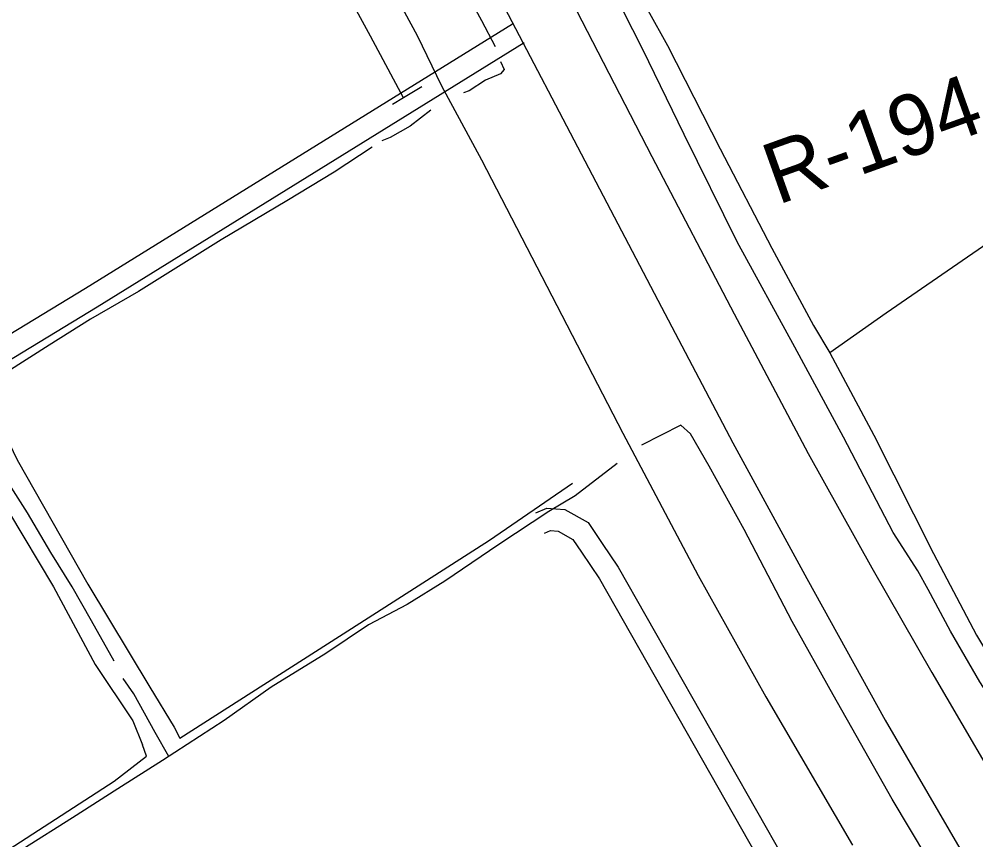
# Model space of a CAD drawing. Extents: x 3324125 to 3362000, y 600753 to 626151.
# Drawn here: x 3330131 to 3331430, y 613099 to 614214 of the extents above; entities that cross this region are included whole.
import ezdxf

# ---------------------------------------------------------------- set-up
doc = ezdxf.new("R2010")
doc.units = 0
for name, color, linetype in [('V-DTCH-CNTR', 7, 'Continuous'), ('V-RAIL-TRAK', 7, 'Continuous'), ('V-RIVR-RANG-IDEN', 7, 'Continuous'), ('V-ROAD-CNTR', 7, 'Continuous'), ('V-TOPO-SHOR', 7, 'Continuous')]:
    doc.layers.add(name, color=color, linetype=linetype)

msp = doc.modelspace()

# ---------------------------------------------------------------- linework, layer by layer
at = {"layer": 'V-DTCH-CNTR'}
for points in [[(3330957.7, 614274.3), (3331010.7, 614177.8), (3331082.2, 614037.5), (3331152.6, 613902.5), (3331209.1, 613797.3), (3331231.5, 613760.5), (3331290.9, 613648.4), (3331372.2, 613487.5), (3331430.4, 613376.6), (3331510.5, 613243.8), (3331602.7, 613085.8)], [(3331480.9, 613933.3), (3331307.9, 613814.1), (3331231.5, 613760.5)], [(3329967.9, 613897.1), (3330014.9, 613810.6), (3330059.1, 613727.8), (3330072, 613718.1), (3330082.6, 613708.4), (3330128, 613614.7), (3330223.6, 613445.8), (3330307.9, 613306), (3330341.1, 613251.9)], [(3330020.6, 613705), (3330062.9, 613630.2), (3330115.9, 613544.7), (3330177.2, 613442.6), (3330233.8, 613337), (3330285, 613260.4), (3330298.1, 613227.7)], [(3330341.1, 613251.9), (3330348.8, 613236.8), (3330581.7, 613385.7), (3330769.2, 613506), (3330882, 613583.3)], [(3329755.3, 612855.6), (3330029.3, 613029.3), (3330259.4, 613178.2), (3330303.3, 613212.2), (3330298.1, 613227.7)]]:
    msp.add_lwpolyline(points, dxfattribs=at)
at = {"layer": 'V-RAIL-TRAK'}
msp.add_lwpolyline([(3330605.3, 614312.9), (3330670.9, 614191.2), (3330704, 614123), (3330758.4, 614022.4), (3330860.7, 613824.8), (3330950.3, 613651.1), (3331052.6, 613457.6), (3331144.3, 613293.1), (3331262.1, 613091.2)], dxfattribs=at)
at = {"layer": 'V-ROAD-CNTR'}
for points in [[(3328654.4, 618531.3), (3329365.9, 617157.1), (3329945, 616043.4), (3330528.3, 614922), (3330989.5, 614026.8), (3331101.4, 613813.5), (3331202.1, 613623.7), (3331288.2, 613468), (3331370, 613325.9), (3331489, 613122.4), (3331566.5, 612992.9), (3331683.8, 612804.9), (3331896.1, 612486.7), (3332030.8, 612296.1), (3332261.4, 611985.3), (3332414.1, 611792.3), (3332593.4, 611567.9), (3332751.8, 611383.2), (3332947.9, 611162.2), (3333176.2, 610911.4), (3333408.7, 610672.1), (3333754.4, 610344.1), (3333997.3, 610124.4), (3334416.3, 609777.9)], [(3328581.7, 618486.8), (3329049, 617590.5), (3329407, 616899.8), (3329876.9, 615987.8), (3330239, 615290.1), (3330685.5, 614428.5), (3331002.8, 613822.2), (3331099.5, 613638), (3331200, 613453.8), (3331306.4, 613261.3), (3331407.9, 613087), (3331494.8, 612942.7), (3331614.1, 612752.9), (3331713.9, 612602.5), (3331866.6, 612380.6), (3332016.4, 612177), (3332147.9, 611993.9), (3332265.1, 611843.6), (3332400.7, 611680.6), (3332500.3, 611558.3), (3332661.3, 611378.2), (3332840.8, 611178.7), (3333031, 610974.2)], [(3330800.3, 614206.8), (3330220.7, 613847.7), (3330058.6, 613749.4)], [(3330816.1, 614181.3), (3330236.3, 613822.2), (3330079, 613726.6)], [(3330832.2, 613543.1), (3330847.1, 613549.4), (3330871.4, 613547.3), (3330903.1, 613529.6), (3330922.2, 613501.4)], [(3330843.8, 613515.4), (3330851.9, 613518.8), (3330862.5, 613517.9), (3330882.2, 613506.9), (3330893.9, 613489.7)], [(3330922.2, 613501.4), (3330944, 613469.2), (3331169.3, 613072.5), (3331314.8, 612840.5)], [(3330893.9, 613489.7), (3330918.5, 613453.4), (3331143.6, 613057.1), (3331289.8, 612823.8)]]:
    msp.add_lwpolyline(points, dxfattribs=at)
at = {"layer": 'V-TOPO-SHOR'}
msp.add_line((3331029.1, 613662.2), (3330975.7, 613635), dxfattribs=at)
for points in [[(3330238.3, 615169.6), (3330246.8, 615172.4), (3330255.3, 615173.7), (3330261.3, 615169.6), (3330275.1, 615147), (3330309.2, 615075.5), (3330353.3, 614988.6), (3330383.3, 614924.4), (3330436, 614823.8), (3330479, 614745.8), (3330502.1, 614693.7), (3330507.4, 614678.3), (3330515.5, 614660.9), (3330527.2, 614639.1), (3330564.5, 614578.1), (3330606.7, 614494.5), (3330677.6, 614365.2), (3330720.6, 614281.2), (3330758.3, 614211.7), (3330776.9, 614176.5)], [(3330652.3, 614106.8), (3330607.4, 614190.7), (3330555.6, 614286.6), (3330504.8, 614388.9), (3330447.5, 614498.4), (3330383.3, 614620.8), (3330335, 614710.7), (3330277.3, 614826.2), (3330221.3, 614932.3), (3330155.4, 615055.9), (3330116.6, 615129)], [(3331854.7, 612684.6), (3331838.4, 612673.6), (3331836.3, 612674.3), (3331751, 612789.3), (3331652.7, 612945.9), (3331632.2, 612984.7), (3331598.8, 613031.7), (3331529.8, 613146.7), (3331476.5, 613244.1), (3331461.5, 613272), (3331434.9, 613313.5), (3331395.3, 613382.2), (3331364.6, 613438.8), (3331350.9, 613463.9), (3331317.5, 613516.4), (3331249.8, 613645.7), (3331183.6, 613768.2), (3331105.7, 613911.2), (3331033.3, 614056.9), (3330977.3, 614172.6), (3330936.3, 614253.7)], [(3330784.2, 614156.3), (3330789.1, 614145.4), (3330784.2, 614139.3), (3330763.6, 614130.8), (3330741.4, 614116.2), (3330734.1, 614113.4)], [(3330677.1, 614121.8), (3330652.3, 614106.8), (3330637.5, 614097.8)], [(3330689.7, 614089.9), (3330661.4, 614068.4), (3330634.3, 614053), (3330622.9, 614048.3)], [(3330610.1, 614039.6), (3330558.4, 614005.6), (3330493.8, 613966.7), (3330404.9, 613913.6), (3330292.6, 613843.6), (3330227.5, 613805.9), (3330171.4, 613770.6), (3330113.6, 613734.2), (3330081.3, 613714.7)], [(3330259.7, 613341.4), (3330228.6, 613396.2), (3330202.6, 613442.2), (3330173.4, 613489.1), (3330141.8, 613542.8), (3330113.5, 613587.7), (3330089.2, 613625.7), (3330067.7, 613662), (3330049.9, 613693.1), (3330042.5, 613706.6)], [(3331680.3, 612558.2), (3331683.7, 612566.3), (3331663, 612596.2), (3331600.1, 612697.9), (3331526.4, 612817.4), (3331465.3, 612914.5), (3331388.1, 613033.4), (3331316, 613154.1), (3331235.9, 613295.5), (3331180, 613395.5), (3331114.8, 613520.2), (3331067.6, 613606.4), (3331042.2, 613650.1), (3331029.1, 613662.2)], [(3330942.6, 613609.9), (3330885.3, 613566.2), (3330849.7, 613544.7), (3330781.8, 613500.1), (3330708.7, 613449.9), (3330657.4, 613418.3), (3330604.9, 613390.7), (3330547.1, 613351.8), (3330472.8, 613306.1), (3330409, 613260.7), (3330325.4, 613206.4), (3330264.4, 613167.9), (3330203, 613128.6), (3330135.5, 613086.1), (3330071.3, 613045.2)], [(3330333.9, 613212), (3330315.3, 613244.7), (3330286.1, 613297.2), (3330271.8, 613317.9)]]:
    msp.add_lwpolyline(points, dxfattribs=at)

# ---------------------------------------------------------------- texts
at = {"layer": 'V-RIVR-RANG-IDEN'}
msp.add_text('R-194.4', height=83, rotation=19.7253, dxfattribs=at).set_placement((3331160.3, 613960.9))

doc.saveas('drawing.dxf')
